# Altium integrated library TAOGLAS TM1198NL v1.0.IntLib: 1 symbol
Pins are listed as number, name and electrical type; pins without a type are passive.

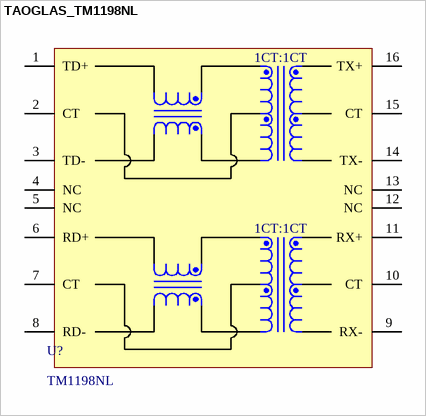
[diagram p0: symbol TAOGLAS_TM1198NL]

## TAOGLAS_TM1198NL
designator U?, comment TM1198NL
LAN 10/100 Base-T transformer Single Port and 16pin SMT; ComponentLibStatus: Created; MFG: Taoglas; Temp_High: +85C; Temp_Low: -40C
footprint TAOGLAS_TM1198NL (LAN 10/100 Base-T transformer Single Port and 16pin SMT)
pins: 1 TD+, 2 CT, 3 TD-, 4 NC, 5 NC, 6 RD+, 7 CT, 8 RD-, 9 RX-, 10 CT, 11 RX+, 12 NC, 13 NC, 14 TX-, 15 CT, 16 TX+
